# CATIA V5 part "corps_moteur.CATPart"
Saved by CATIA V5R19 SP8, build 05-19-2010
Part number: corps_moteur
Revision: ANY
Definition: UNKNOWN
Nomenclature: 9
Source: Unknown
Bounding box of the stored display mesh (mm): x -71.005 to -14.505, y -17.8 to 17.8, z -17.8 to 0.001
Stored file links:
  D:\Documents\1_Travail\2- 2I2D\1 - Cours et TD\2- TD\3-TD Assemblage\Pompe AirMan_Corrigé\corps_moteur.CATPart
  D:\Documents\1_Travail\2- 2I2D\1 - Cours et TD\2- TD\3-TD Assemblage\Pompe AirMan\0-PompeAirman.CATProduct
  D:\Documents\1_Travail\2- 2I2D\1 - Cours et TD\2- TD\3-TD Assemblage\Pompe AirMan\Corps_Reducteur.CATPart
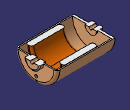
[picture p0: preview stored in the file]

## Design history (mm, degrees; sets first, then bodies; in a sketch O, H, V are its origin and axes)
Set1
  DatumCurve1
Body1 "Révolution3" (main body)
  Solid1: solid without history
Body2 "Enlèv. mat.-Extru.1"
  Solid2: solid without history
  Sketch1 on face of Solid2, origin (-18.0052, 0, 0), H (0, 1, 0), V (0, 0, 1)
    circle A1 centre (0, -12.255) radius 1.25
    reference projected arc E1 centre (0, -12.255) radius 1.25 from (0, -13.505) to (0, -11.005) ccw from edge [face of Solid2 | face of Solid2]
    coincidence: A1 E1
  Pad1: profile Sketch1, direction (1, 0, 0), up to face of Solid2
  Sketch2 on face of Solid2, origin (-19.0052, 0, 0), H (0, -1, 0), V (0, 0, 1)
    circle A1 centre (0, -12.2561) radius 1.25
    reference projected point E1 (0, -12.2561) from edge of DatumCurve1
    radius A1 = 1.25
    concentricity: E1 A1
  Pocket1: profile Sketch2, direction (1, 0, 0), through (limit type 3)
